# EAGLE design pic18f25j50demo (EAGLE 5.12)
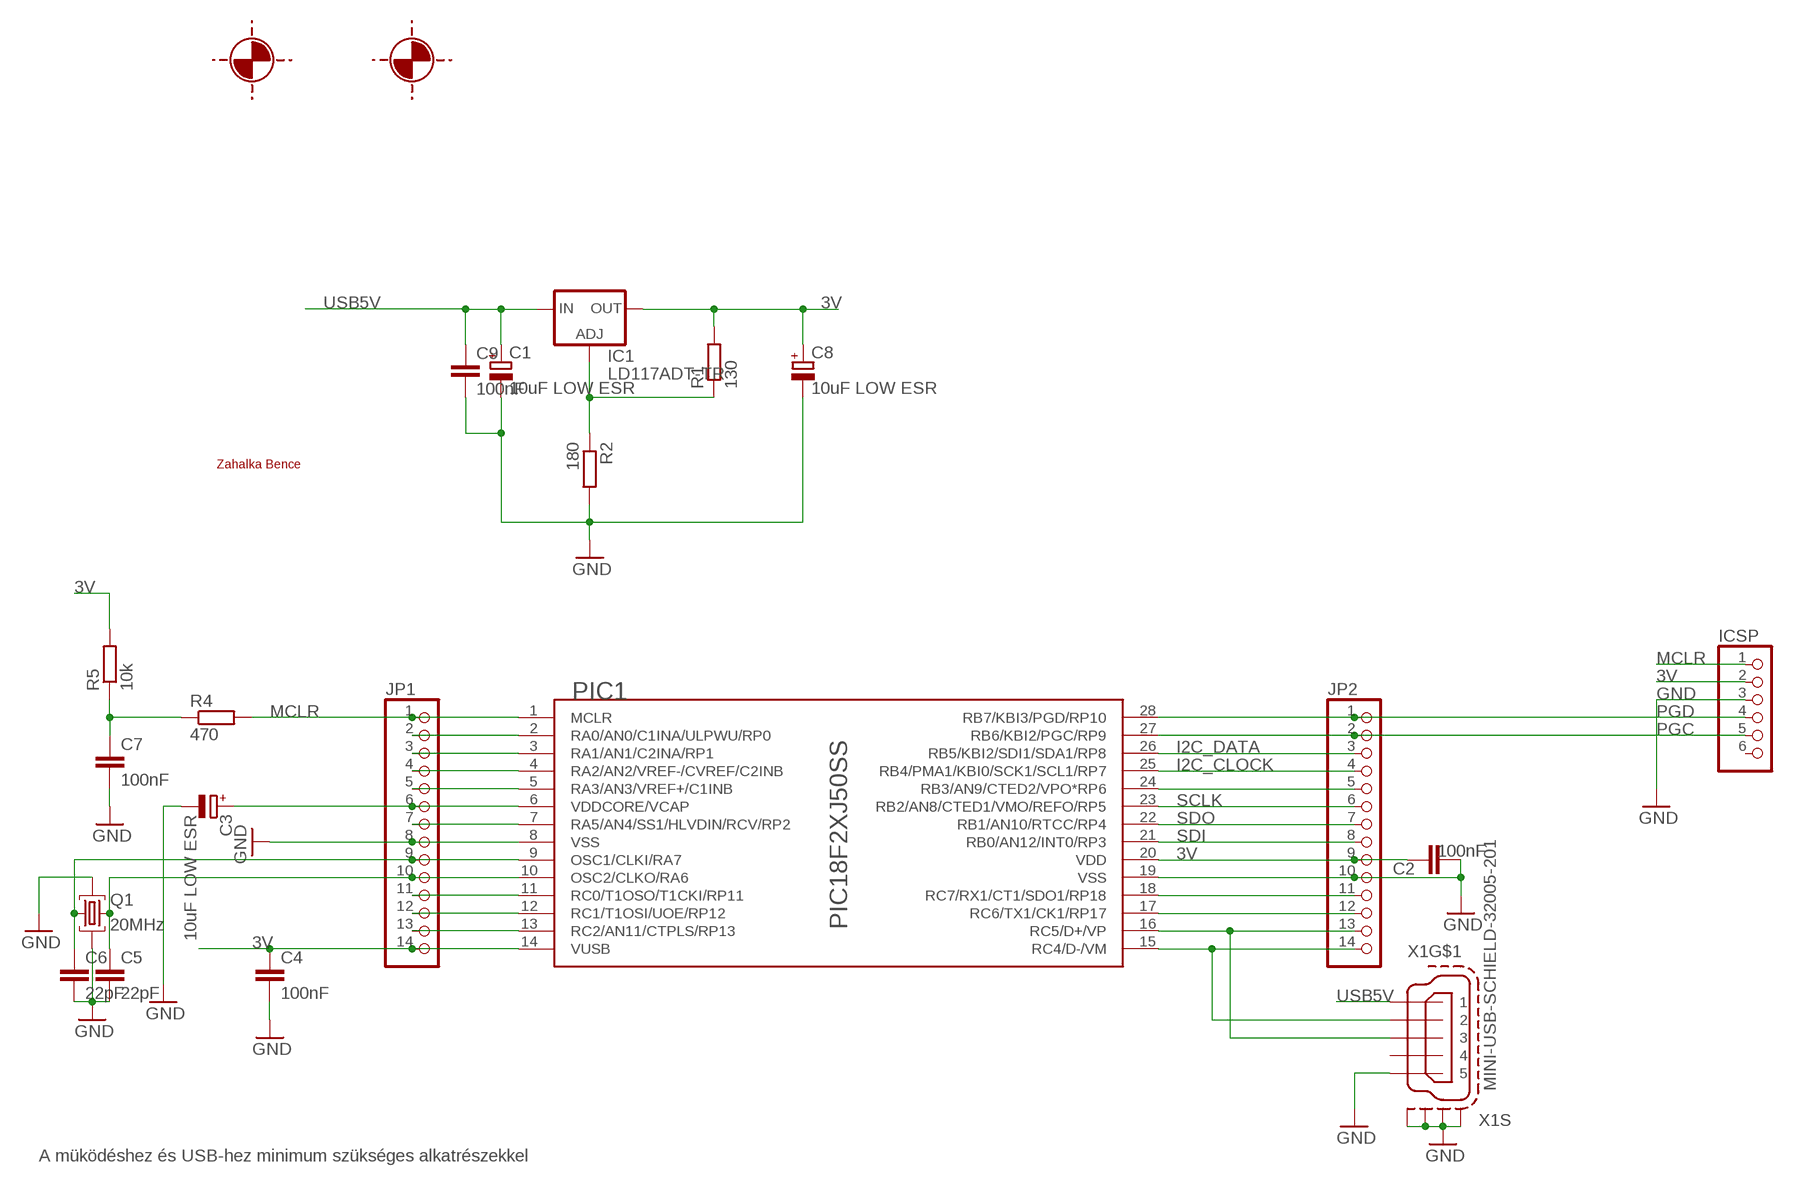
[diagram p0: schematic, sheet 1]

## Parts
C1  10uF LOW ESR  CPOL-EU153CLV-0505  [153CLV-0505]
C2  100nF  C-EUC0805  [C0805]
C3  10uF LOW ESR  CPOL-EU153CLV-0505  [153CLV-0505]
C4  100nF  C-EUC0805  [C0805]
C5  22pF  C-EUC0402  [C0402]
C6  22pF  C-EUC0402  [C0402]
C7  100nF  C-EUC0805  [C0805]
C8  10uF LOW ESR  CPOL-EU153CLV-0505  [153CLV-0505]
C9  100nF  C-EUC0805  [C0805]
IC1  LD117ADT-TR  [DPACK]
ICSP  PINHD-1X6/90  [1X06/90]
JP1  PINHD-1X14  [1X14]
JP2  PINHD-1X14  [1X14]
PIC1  PIC18F2XJ50SS  [SSOP28]
Q1  20MHz  NXK32-CRYSTAL  [NXK-32]
R1  130  R-EU_R0805  [R0805]
R2  180  R-EU_R0805  [R0805]
R4  470  R-EU_R0805  [R0805]
R5  10k  R-EU_R0805  [R0805]
U$2  JELOLO  [JELOLO]
U$3  JELOLO  [JELOLO]
X1  MINI-USB-SCHIELD-32005-201  [32005-201]
ZB1  ZB  [ZB]

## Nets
2: JP1.2 PIC1.2(RA0/AN0/C1INA/ULPWU/RP0)
3: JP1.3 PIC1.3(RA1/AN1/C2INA/RP1)
3V: C2.1 C4.1 C8.+ IC1.4(OUT) ICSP.2 JP1.14 JP2.9 PIC1.14(VUSB) PIC1.20(VDD) R1.2 R5.2
4: JP1.4 PIC1.4(RA2/AN2/VREF-/CVREF/C2INB)
5: JP1.5 PIC1.5(RA3/AN3/VREF+/C1INB)
6: C3.+ JP1.6 PIC1.6(VDDCORE/VCAP)
7: JP1.7 PIC1.7(RA5/AN4/SS1/HLVDIN/RCV/RP2)
9: C6.1 JP1.9 PIC1.9(OSC1/CLKI/RA7) Q1.P$1
10: C5.1 JP1.10 PIC1.10(OSC2/CLKO/RA6) Q1.P$3
11: JP1.11 PIC1.11(RC0/T1OSO/T1CKI/RP11)
12: JP1.12 PIC1.12(RC1/T1OSI/UOE/RP12)
13: JP1.13 PIC1.13(RC2/AN11/CTPLS/RP13)
17: JP2.12 PIC1.17(RC6/TX1/CK1/RP17)
18: JP2.11 PIC1.18(RC7/RX1/CT1/SDO1/RP18)
24: JP2.5 PIC1.24(RB3/AN9/CTED2/VPO*RP6)
D+: JP2.13 PIC1.16(RC5/D+/VP) X1.3
D-: JP2.14 PIC1.15(RC4/D-/VM) X1.2
GND: C1.- C2.2 C3.- C4.2 C5.2 C6.2 C7.2 C8.- C9.2 ICSP.3 JP1.8 JP2.10 PIC1.8(VSS) PIC1.19(VSS) Q1.P$2(GND) Q1.P$4(GND) R2.2 X1.5 X1.M1(S:S1) X1.M2(S:S2) X1.M3(S:S3) X1.M4(S:S4)
I2C_CLOCK: JP2.4 PIC1.25(RB4/PMA1/KBI0/SCK1/SCL1/RP7)
I2C_DATA: JP2.3 PIC1.26(RB5/KBI2/SDI1/SDA1/RP8)
MCLR: ICSP.1 JP1.1 PIC1.1(MCLR) R4.2
N$11: C7.1 R4.1 R5.1
N$17: IC1.1(ADJ) R1.1 R2.1
PGC: ICSP.5 JP2.2 PIC1.27(RB6/KBI2/PGC/RP9)
PGD: ICSP.4 JP2.1 PIC1.28(RB7/KBI3/PGD/RP10)
SCLK: JP2.6 PIC1.23(RB2/AN8/CTED1/VMO/REFO/RP5)
SDI: JP2.8 PIC1.21(RB0/AN12/INT0/RP3)
SDO: JP2.7 PIC1.22(RB1/AN10/RTCC/RP4)
USB5V: C1.+ C9.1 IC1.3(IN) X1.1
Unconnected: ICSP.6 X1.4

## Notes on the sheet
- A müködéshez és USB-hez minimum szükséges alkatrészekkel

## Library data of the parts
C1 C3 C8 = rcl:CPOL-EU: POLARIZED CAPACITOR, European symbol
C2 C4-C7 C9 = rcl:C-EU: CAPACITOR, European symbol
IC1 = v-reg:LD117A?*: Low drop fixed and adjustable positive voltage regulators 1 A Source: http://www.st.com/stonline/products/literature/ds/7194/ld1117axx.pdf
ICSP = pinhead:PINHD-1X6: PIN HEADER
JP1 JP2 = sajat:PINHD-1X14: PIN HEADER
PIC1 = sajat:PIC18F2XJ50: 28 pin, Low-Power, High-Performance USB Microcontroller with nanoWatt XLP&#0153; technology.
Q1 = sajat:NXK32-CRYSTAL: SMD TYPE CERAMIC CRYSTAL (SMD 3.2 x 2.5)
R1 R2 R4 R5 = rcl:R-EU_: RESISTOR, European symbol
U$2 U$3 = sajat:JELOLO: Ez egy pozicionalo marker, hogy ketoldalas nyaknal konnyebb legyen osszeigazitani a ket lapot.
X1 = con-cypressindustries:MINI-USB-SCHIELD-: MINI USB-B Conector Source: www.cypressindustries.com; OC_FARNELL: unknown; OC_NEWARK: unknown
ZB1 = sajat:ZB: Zahalka Bence monogram

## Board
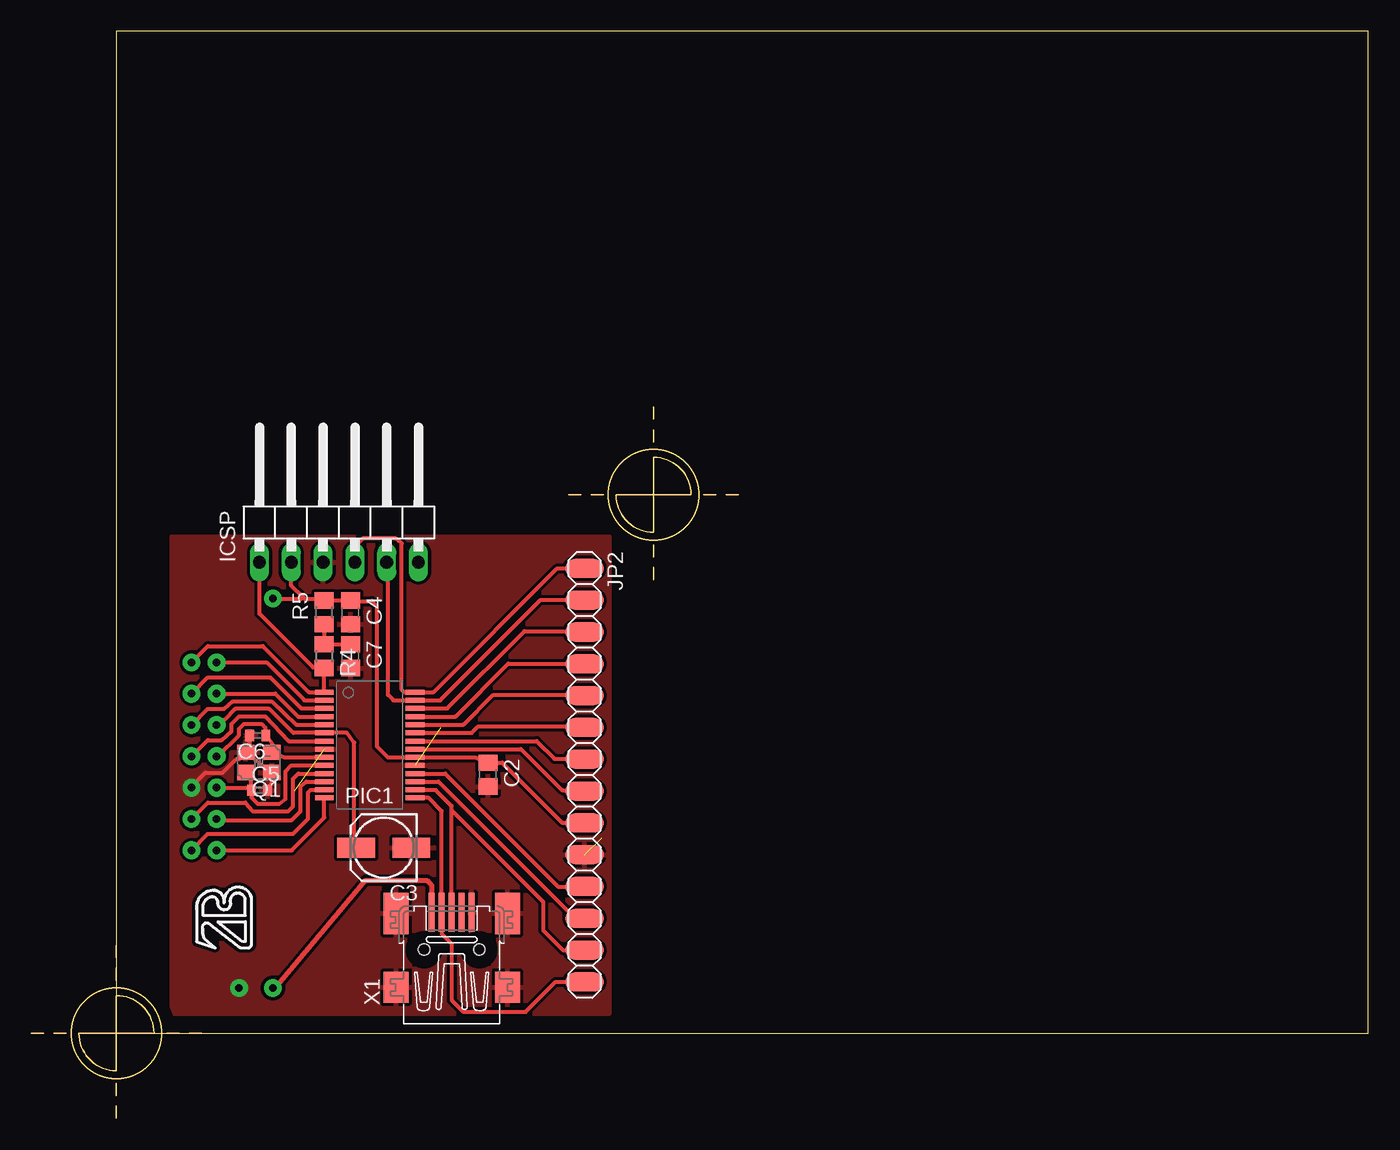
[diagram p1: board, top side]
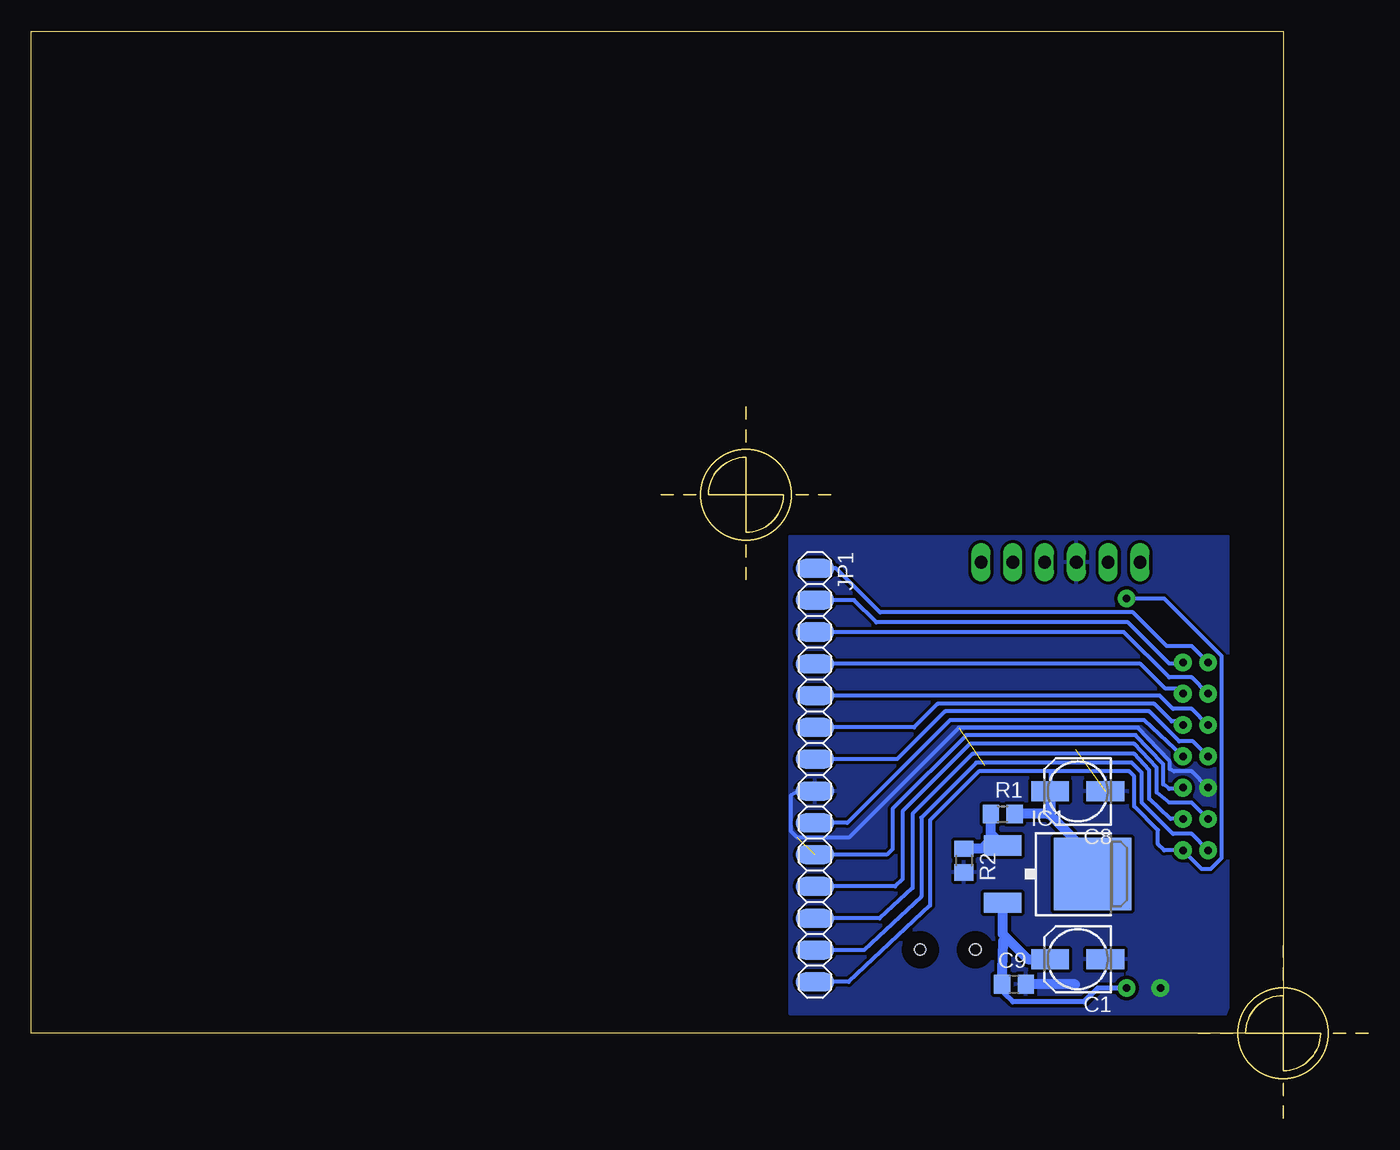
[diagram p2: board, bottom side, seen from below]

Size 106.8 x 86.8 mm. Coordinates in mm from the lower left corner, seen from the top.
Outline: 6.8,6.8 106.8,6.8 106.8,86.8 6.8,86.8 6.8,6.8
Copper layers (1*16): Top 0.035mm / dielectric 1.5mm / Bottom 0.035mm
Design rules "default *": minimum track width 10mil, minimum drill 20mil, track to track 8mil, track to pad 8mil, pad to pad 8mil, via to via 8mil, smd to smd 8mil, copper to edge 40mil, drill to drill 8mil, minimum pad ring 10mil, minimum via ring 8mil, stop-mask expansion 4mil, vias tented up to drill 0mil, thermal gap 10mil

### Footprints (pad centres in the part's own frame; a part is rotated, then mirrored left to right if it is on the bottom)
153CLV-0505 = smd 3 x 1.6: + 2.2,0; - -2.2,0
C0805 = smd 1.3 x 1.5: 1 -0.95,0; 2 0.95,0
C0402 = smd 0.7 x 0.9: 1 -0.65,0; 2 0.65,0
DPACK = smd 1.6 x 3: 1 -2.28,-4.8; 3 2.28,-4.8 | smd 5.8 x 6.2: 4 0,2.38
1X06/90 = drill 1.016 long: 1 -6.35,-3.81; 2 -3.81,-3.81; 3 -1.27,-3.81; 4 1.27,-3.81; 5 3.81,-3.81; 6 6.35,-3.81
1X14 = smd 1.524 x 3.048: 1 -16.51,0; 2 -13.97,0; 3 -11.43,0; 4 -8.89,0; 5 -6.35,0; 6 -3.81,0; 7 -1.27,0; 8 1.27,0; 9 3.81,0; 10 6.35,0; 11 8.89,0; 12 11.43,0; 13 13.97,0; 14 16.51,0
SSOP28 = smd 1.5 x 0.4: 1 -3.625,4.225; 2 -3.625,3.575; 3 -3.625,2.925; 4 -3.625,2.275; 5 -3.625,1.625; 6 -3.625,0.975; 7 -3.625,0.325; 8 -3.625,-0.325; 9 -3.625,-0.975; 10 -3.625,-1.625; 11 -3.625,-2.275; 12 -3.625,-2.925; 13 -3.625,-3.575; 14 -3.625,-4.225; 15 3.625,-4.225; 16 3.625,-3.575; 17 3.625,-2.925; 18 3.625,-2.275; 19 3.625,-1.625; 20 3.625,-0.975; 21 3.625,-0.325; 22 3.625,0.325; 23 3.625,0.975; 24 3.625,1.625; 25 3.625,2.275; 26 3.625,2.925; 27 3.625,3.575; 28 3.625,4.225
NXK-32 = smd 1.4 x 1.2: P$1 -1.05,-0.8; P$2 -1.05,0.8; P$3 1.05,0.8; P$4 1.05,-0.8
R0805 = smd 1.3 x 1.5: 1 -0.95,0; 2 0.95,0
32005-201 = smd 3.1 x 0.5: 1 3,1.6; 2 3,0.8; 3 3,0; 4 3,-0.8; 5 3,-1.6 | smd 2.5 x 2: M1 -3,-4.45; M2 -3,4.45 | smd 3.3 x 2: M3 2.9,4.45; M4 2.9,-4.45 | hole 0.9: 0,2.2; 0,-2.2

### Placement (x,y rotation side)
C1  23.2,12.7 180 bottom
C2  36.48,27.44 270 top
C3  28.15,21.61 180 top
C4  25.5,40.4 270 top
C5  18.23,26.19 0 top
C6  18.1,30.57 180 top
C7  25.5,36.9 270 top
C8  23.2,26.1 180 bottom
C9  28.3,10.7 0 bottom
IC1  24.4,19.5 270 bottom
ICSP  24.58,48.21 0 top
JP1  44.2,27.4 270 bottom
JP2  44.2,27.4 270 top
PIC1  27.03,29.8 0 top
Q1  18.18,28.41 180 top
R1  29.2,24.3 0 bottom
R2  32.3,20.58 270 bottom
R4  23.4,36.9 270 top
R5  23.4,40.4 90 top
U$2  6.8,6.8 0 top
U$3  49.7,49.8 0 top
X1  33.58,13.46 90 top
ZB1  15.3,15.9 90 top

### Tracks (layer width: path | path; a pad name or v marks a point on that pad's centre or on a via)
2  (via drill 0.6 pad 1.42)
  Top 0.305: PIC1.2 21.82,33.38 18.8,36.4 v14.8,36.4
  Bottom 0.305: JP1.2 41.07,41.37 39.3,39.6 19.2,39.6 15.9,36.3 14.9,36.3 v14.8,36.4
3  (via drill 0.6 pad 1.42)
  Top 0.305: PIC1.3 21.57,32.73 19.1,35.2 14.1,35.2 v12.8,33.9
  Bottom 0.305: JP1.3 19.53,38.83 15.9,35.2 14.1,35.2 v12.8,33.9
3V  (via drill 0.6 pad 1.42)
  Top 0.305: PIC1.14 23.41,24 20.8,21.4 v14.8,21.4 | ICSP.2 20.77,42.53 21.7,41.6 | 21.7,41.6 21.8,41.5 23.4,41.5 R5.2 C4.1 | C4.1 25.37,41.39 | JP2.9 42.4,23.6 37.61,28.39 C2.1 35.46,28.82 PIC1.20 28.48,28.82 27.6,29.7 27.6,40.9 27.2,41.3 25.55,41.3 C4.1 | v19.3,41.5 21.6,41.5 21.7,41.6
  Bottom 0.305: JP1.14 41.51,10.89 35,17 35,23.8 31.1,27.7 25.4,27.7 | 25.4,27.7 19.1,27.7 18.7,27.3 18.7,24.9 16.8,23 16.8,21.9 16.3,21.4 v14.8,21.4 13.3,19.9 12.6,19.9 11.7,20.8 11.7,36.9 16.3,41.5 v19.3,41.5 | 25.4,27.7 25.4,26
  Bottom 0.813: IC1.4 22.02,20.82 25.4,24.2 25.4,24.5 | 25.4,24.5 25.4,26 C8.+ | 25.4,24.5 25.6,24.3 R1.2
4  (via drill 0.6 pad 1.42)
  Top 0.305: PIC1.4 21.32,32.07 19.5,33.9 v14.8,33.9
  Bottom 0.305: JP1.4 18.19,36.29 16.2,34.3 15.2,34.3 v14.8,33.9
5  (via drill 0.6 pad 1.42)
  Top 0.305: PIC1.5 21.17,31.42 19.2,33.3 16.1,33.3 15.4,32.7 14.1,32.7 v12.8,31.4
  Bottom 0.305: JP1.5 16.65,33.75 15.6,32.7 14.1,32.7 v12.8,31.4
6  (via drill 0.6 pad 1.42)
  Top 0.305: v14.8,31.4 15.2,31.8 15.4,31.8 16.3,32.7 19,32.7 20.92,30.77 PIC1.6 25.23,30.77 25.8,30 25.8,22.86 C3.+
  Bottom 0.305: JP1.6 36.29,31.21 34.4,33.1 17.1,33.1 15.7,31.7 15.1,31.7 v14.8,31.4
7  (via drill 0.6 pad 1.42)
  Top 0.305: PIC1.7 20.57,30.12 18.7,32.1 16.6,32.1 16,31.5 16,30.9 15.2,30.2 14.1,30.2 v12.8,28.9
  Bottom 0.305: JP1.7 37.63,28.67 33.8,32.5 17.5,32.5 15.1,30.1 14,30.1 v12.8,28.9
9  (via drill 0.6 pad 1.42)
  Top 0.305: PIC1.9 20.21,28.82 Q1.P$1 19.35,29.69 C6.1 18.7,30.62 18.7,31.2 18.4,31.5 17,31.5 16.6,31.1 16.6,30.6 14.9,28.9 v14.8,28.9
  Bottom 0.305: JP1.9 41.61,23.59 33.4,31.8 17.9,31.8 v14.8,28.9
10  (via drill 0.6 pad 1.42)
  Top 0.305: PIC1.10 20.77,28.17 20.3,27.7 20.3,25.5 19.8,25.1 18.1,25.1 17.6,25.6 17.6,26.17 C5.1 | C5.1 17.58,27.16 Q1.P$3 | v14.8,26.4 17.37,26.4 C5.1
  Bottom 0.305: JP1.10 38.45,21.05 38,21.5 38,24.7 32.1,30.6 18.6,30.6 16.38,28.28 16.38,26.66 15.9,26.3 14.9,26.3 v14.8,26.4
11  (via drill 0.6 pad 1.42)
  Top 0.305: PIC1.11 21.32,27.52 20.9,27.1 20.9,24.9 20.5,24.5 17.7,24.5 17.1,25.2 14.1,25.2 v12.8,23.9
  Bottom 0.305: JP1.11 37.79,18.51 37.2,19.1 37.2,24.5 31.8,29.9 18.7,29.9 16.9,28 16.9,26 15.9,25.2 14.1,25.2 v12.8,23.9
12  (via drill 0.6 pad 1.42)
  Top 0.305: PIC1.12 21.98,26.88 21.5,26.5 21.5,24.5 20.8,23.8 14.9,23.8 v14.8,23.9
  Bottom 0.305: JP1.12 39.03,15.97 36.4,18.4 36.4,24.3 31.6,29.1 18.7,29.1 17.5,27.8 17.5,25.5 15.8,23.9 v14.8,23.9
13  (via drill 0.6 pad 1.42)
  Top 0.305: PIC1.13 22.32,26.23 22.1,26 22.1,23.9 20.9,22.7 14.1,22.7 v12.8,21.4
  Bottom 0.305: JP1.13 40.27,13.43 35.7,17.7 35.7,24 31.3,28.4 18.9,28.4 18.1,27.6 18.1,25.2 15.6,22.7 14.1,22.7 v12.8,21.4
17
  Top 0.305: JP2.12 43.43,15.97 32.52,26.88 PIC1.17
18
  Top 0.305: PIC1.18 33.07,27.52 42.1,18.5 JP2.11
24
  Top 0.305: PIC1.24 34.52,31.42 36.9,33.8 44.15,33.8 JP2.5
D+
  Top 0.305: X1.3 33.58,24.6 | 33.58,24.6 33.58,24.92 32.3,26.2 30.68,26.2 PIC1.16 | JP2.13 42.47,13.43 40.9,15 40.9,17.28 33.58,24.6
D-
  Top 0.305: PIC1.15 31.73,25.57 32.78,24.52 X1.2 32.8,16.44 32.8,14.7 33.6,13.9 33.6,9.4 34.5,8.5 39.5,8.5 41.89,10.89 JP2.14
GND  (via drill 0.6 pad 1.42)  (3 unrouted)
  Top 0.305: Q1.P$4 Q1.P$2 19.48,27.26 C5.2 | C6.2 17.45,29.21 Q1.P$4 | v12.8,26.4 12.8,26.5 13.9,27.6 15.3,27.6 16.4,28.7 16.62,28.7 Q1.P$4
  Bottom 0.305: JP1.8 45.57,26.13 46.1,25.8 46.1,22.9 45.6,22.4 41.5,22.4 32.7,31.2 18.4,31.2 15.85,28.5 15.85,27.9 15.5,27.7 14.1,27.7 v12.8,26.4
  Bottom 0.813: C8.- 21,25.9 | C1.- 21.4,12.7 | 23.4,10.7 C9.2
  other vias: 16.6,10.4
  pour Top (isolate 0.254): 46.2,8.4 46.2,46.4 11.2,46.4 11.2,8.4
  pour Bottom (isolate 0.254): 11.2,46.4 46.2,46.4 46.2,8.4 11.2,8.4
I2C_CLOCK
  Top 0.305: PIC1.25 33.88,32.07 38.1,36.3 JP2.4
I2C_DATA
  Top 0.305: PIC1.26 33.23,32.73 39.4,38.9 44.13,38.9 JP2.3
MCLR  (via drill 0.6 pad 1.42)
  Top 0.305: v12.8,36.4 14.1,37.7 18.5,37.7 22.17,34.02 PIC1.1 R4.2 23.35,36 22.5,36 18.23,40.27 ICSP.1
  Bottom 0.305: JP1.1 42.51,43.91 39,40.4 18.8,40.4 16.1,37.7 14.1,37.7 v12.8,36.4
N$11
  Top 0.305: R5.1 R4.1 C7.1
N$17
  Bottom 0.813: R1.1 30.15,22.73 29.91,22.49 | IC1.1 29.91,22.49 | R2.1 30.87,21.53 29.91,22.49
PGC
  Top 0.305: ICSP.5 28.5,44.29 28.5,33.8 28.92,33.38 PIC1.27 32.67,33.38 40.7,41.4 44.17,41.4 JP2.2
PGD
  Top 0.305: ICSP.4 25.8,44.45 25.8,45.6 26.5,46.3 29.1,46.3 29.6,45.9 29.6,34.2 29.77,34.02 PIC1.28 32.12,34.02 42.01,43.91 JP2.1
SCLK
  Top 0.305: PIC1.23 35.17,30.77 35.7,31.3 44.11,31.3 JP2.6
SDI
  Top 0.305: PIC1.21 39.12,29.48 42.4,26.2 44.13,26.2 JP2.8
SDO
  Top 0.305: PIC1.22 40.38,30.12 41.8,28.7 44.17,28.7 JP2.7
USB5V  (via drill 0.6 pad 1.42)
  Top 0.406: X1.1 31.98,18.58 31.6,19 26.7,19 19.5,10.4 v19.3,10.4
  Bottom 0.406: v19.3,10.4 21.6,10.4 22.7,9.3 28.4,9.3 29.1,10 C9.1
  Bottom 0.813: IC1.3 29.2,14.7 28.9,14.4 | 28.9,14.4 27.2,12.7 C1.+ | C9.1 29.15,14.15 28.9,14.4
